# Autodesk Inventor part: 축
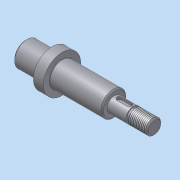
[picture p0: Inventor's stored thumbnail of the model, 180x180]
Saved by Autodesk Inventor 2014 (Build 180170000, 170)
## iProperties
Created: 2015-03
Part Number: 축
Material: 강
Document SubType Name: Modeling
Designer: KYOUNG IL JANG
Density: 1 g/cm^3
Appearance: 강철
CustomPartVersion: 1
Author: KYOUNG IL JANG
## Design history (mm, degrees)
sketch "스케치5"
  geometry: L1 (0, 0)-(103, 0); L2 (0, 0)-(103, 0); L3 (103, 0)-(103, 6); L4 (71, 6)-(71, 10); L5 (71, 10)-(29, 10); L6 (29, 10)-(29, 15); L7 (29, 15)-(21, 15); L8 (21, 15)-(21, 10); L9 (21, 10)-(0, 10); L10 (0, 10)-(0, 0); L11 (86, 6)-(86, 5); L12 (86, 5)-(88, 5); L13 (88, 5)-(88, 6); L14 (103, 6)-(88, 6); L15 (86, 6)-(71, 6)
  constraints: 31 end point, 12 perpendicular, 9 parallel, 1 collinear, 1 horizontal
  dimensions: "d43" = 20 diameter of L9 L1; "d44" = 30 diameter of L7 L1; "d45" = 20 diameter of L5 L2; "d47" = 8 distance of L6.end L7.end; "d48" = 32 distance between parallel lines of L3 L4; "d49" = 42 distance between parallel lines of L4 L6; "d50" = 21 distance of L8.end L9.end; "d52" = 12 diameter of L14 L1; "d53" = 15 distance between parallel lines of L3 L13; "d54" = 2 distance of L11.end L12.end; "d55" = 1 distance between parallel lines of L14 L12
revolve "회전4" sketch "스케치5" stored, may be unused: angle "d51" = 90 deg
feature "스레드6" dims "d56" = 10, "d57" = 0
chamfer "모따기6" distance "d32" = 1; stored, may be unused: second distance "d33" = 0.4, angle "d34" = 45 deg
chamfer "모따기5" distance "d27" = 1; stored, may be unused: second distance "d28" = 0.125, angle "d29" = 45 deg
fillet "모깎기1" dims "d17" = 0.3
fillet "모깎기2" dims "d18" = 0.3
chamfer "모따기3" distance "d19" = 1; stored, may be unused: second distance "d20" = 1, angle "d21" = 45 deg
node "작업 평면1"
sketch "스케치6"
  geometry: L1 (-3.5, 2)-(4.5, 2); L2 (4.5, -2)-(-3.5, -2); L3 (-7.5, 9)-(-7.5, -9) reference; A1 r 2 centre (4.5, 0) between (4.5, -2) and (4.5, 2); A2 r 2 centre (-3.5, 0) between (-3.5, 2) and (-3.5, -2); 1 further point
  constraints: 4 end point, 4 point on circle, 4 tangent, 2 centre point, 1 horizontal, 1 horizontal alignment, 1 parallel
  dimensions: "d59" = 2 distance edge to line of A2 L3; "d60" = 12 dimension on A1 A2; "d61" = 4 distance between parallel lines of L2 L1
extrude "돌출1" cut sketch "스케치6" distance "d62" = 2.3; taper "d63" = 0 deg
node "솔리드1"
node "솔리드2"
other parameters: "d46" = 12
